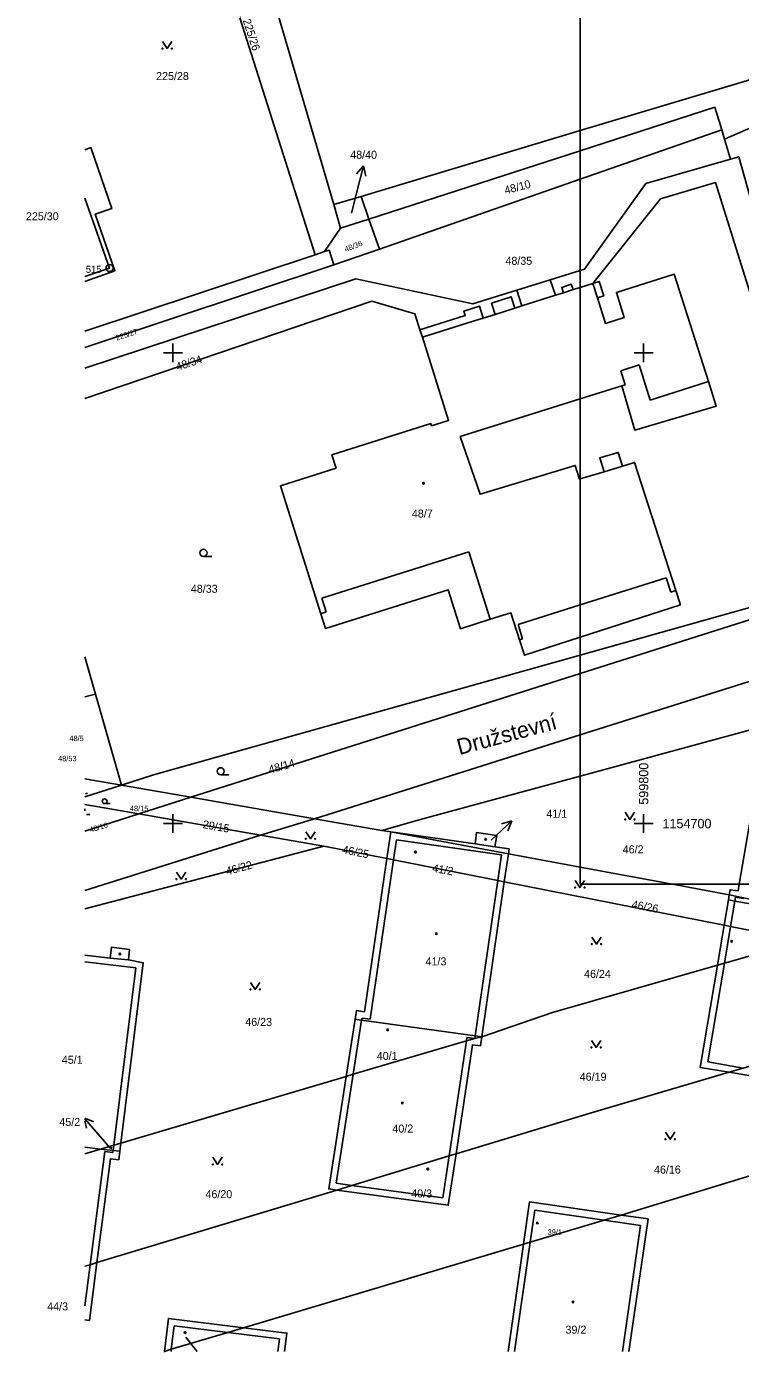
# Model space of a CAD drawing. Extents: x -599866 to -590076, y -1178039 to -1154526.
# Drawn here: x -599865.6 to -599789.7, y -1154756.1 to -1154615.4 of the extents above; entities that cross this region are included whole.
import ezdxf

# ---------------------------------------------------------------- set-up
doc = ezdxf.new("R2010")
doc.units = 0
for name, color, linetype in [('KN', 7, 'Continuous'), ('Rám', 7, 'Continuous'), ('Vrstva 5', 7, 'Continuous')]:
    doc.layers.add(name, color=color, linetype=linetype)

msp = doc.modelspace()

# ---------------------------------------------------------------- linework, layer by layer
at = {"layer": 'KN'}
for p, q in [((-599849.84, -1154592.53), (-599834.91, -1154639.59)), ((-599832.92, -1154634.27), (-599842.8, -1154600.57)), ((-599779.98, -1154622.34), (-599791.41, -1154627.32)), ((-599806.74, -1154631.58), (-599791.7, -1154626.34)), ((-599791.41, -1154627.32), (-599791.7, -1154626.34)), ((-599790.77, -1154629.45), (-599791.41, -1154627.32)), ((-599830.49, -1154633.05), (-599829.76, -1154630.14)), ((-599829.76, -1154630.14), (-599830.49, -1154630.99)), ((-599829.76, -1154630.14), (-599829.52, -1154631.23)), ((-599828.05, -1154639.01), (-599806.74, -1154631.58)), ((-599856.74, -1154641.01), (-599859.38, -1154633.6)), ((-599830.02, -1154633.4), (-599832.92, -1154634.27)), ((-599832.92, -1154634.27), (-599832.19, -1154636.77)), ((-599831.02, -1154635.16), (-599830.49, -1154633.05)), ((-599830.02, -1154633.4), (-599829.18, -1154635.8)), ((-599832.19, -1154636.77), (-599833.89, -1154639.25)), ((-599829.18, -1154635.8), (-599832.19, -1154636.77)), ((-599829.18, -1154635.8), (-599828.05, -1154639.01)), ((-599834.91, -1154639.59), (-599833.89, -1154639.25)), ((-599828.05, -1154639.01), (-599832.9, -1154640.67)), ((-599832.9, -1154640.67), (-599859.38, -1154649.44)), ((-599856.74, -1154641.01), (-599859.38, -1154641.89)), ((-599809.93, -1154642.24), (-599813.46, -1154643.34)), ((-599805.39, -1154642.63), (-599804.9, -1154644.17)), ((-599812.94, -1154645.02), (-599809.38, -1154643.89)), ((-599808.52, -1154643.62), (-599807.5, -1154643.3)), ((-599815.77, -1154645.92), (-599813.7, -1154645.26)), ((-599823.51, -1154648.36), (-599818.69, -1154646.84)), ((-599818.69, -1154646.84), (-599817.04, -1154646.32)), ((-599800.49, -1154651.29), (-599802.44, -1154651.91)), ((-599802.44, -1154651.91), (-599801.96, -1154653.41)), ((-599799.3, -1154655.03), (-599800.49, -1154651.29)), ((-599801.96, -1154653.41), (-599802.33, -1154653.52)), ((-599793.1, -1154653.06), (-599799.3, -1154655.03)), ((-599804.21, -1154662.63), (-599802.26, -1154662.04)), ((-599846.76, -1154671.63), (-599845.88, -1154671.63)), ((-599818.56, -1154671.14), (-599834.18, -1154676.08)), ((-599816.29, -1154678.31), (-599818.56, -1154671.14)), ((-599797.59, -1154673.91), (-599806.74, -1154676.78)), ((-599797.1, -1154675.43), (-599797.59, -1154673.91)), ((-599834.18, -1154676.08), (-599833.72, -1154677.53)), ((-599779.39, -1154675.37), (-599806.74, -1154684.06)), ((-599796.58, -1154675.26), (-599797.1, -1154675.43)), ((-599833.72, -1154677.53), (-599834.28, -1154677.71)), ((-599806.74, -1154676.78), (-599813.34, -1154678.85)), ((-599813.34, -1154678.85), (-599812.86, -1154680.37)), ((-599812.86, -1154680.37), (-599813.19, -1154680.48)), ((-599806.74, -1154684.06), (-599848.12, -1154697.2)), ((-599858.24, -1154686.27), (-599859.38, -1154686.55)), ((-599855.48, -1154695.93), (-599858.24, -1154686.27)), ((-599806.74, -1154694.96), (-599786.94, -1154689.6)), ((-599859.38, -1154695.26), (-599855.48, -1154695.93)), ((-599855.48, -1154695.93), (-599859.38, -1154697.17)), ((-599855.48, -1154695.93), (-599848.12, -1154697.2)), ((-599844.93, -1154694.82), (-599844.05, -1154694.82)), ((-599823.45, -1154699.48), (-599806.74, -1154694.96)), ((-599859.28, -1154696.84), (-599859.09, -1154696.77)), ((-599848.12, -1154697.2), (-599853.64, -1154698.96)), ((-599848.12, -1154697.2), (-599834.98, -1154699.48)), ((-599859.38, -1154697.96), (-599853.64, -1154698.96)), ((-599853.64, -1154698.96), (-599859.38, -1154700.79)), ((-599857.26, -1154697.88), (-599856.67, -1154697.88)), ((-599840.69, -1154701.22), (-599853.64, -1154698.96)), ((-599859.2, -1154699.05), (-599858.84, -1154699.05)), ((-599840.69, -1154701.22), (-599834.98, -1154699.48)), ((-599834.98, -1154699.48), (-599827.8, -1154700.72)), ((-599827.8, -1154700.72), (-599823.45, -1154699.48)), ((-599816.21, -1154701.77), (-599814.02, -1154699.72)), ((-599814.02, -1154699.72), (-599815.09, -1154700.04)), ((-599814.02, -1154699.72), (-599814.41, -1154700.77)), ((-599840.69, -1154701.22), (-599833.96, -1154702.4)), ((-599827.8, -1154700.72), (-599826.85, -1154700.87)), ((-599826.85, -1154700.87), (-599827.27, -1154703.72)), ((-599817.9, -1154702.14), (-599826.85, -1154700.87)), ((-599826.85, -1154700.87), (-599814.37, -1154703.21)), ((-599826.58, -1154703.86), (-599826.27, -1154701.73)), ((-599826.27, -1154701.73), (-599815.09, -1154703.32)), ((-599827.27, -1154703.72), (-599833.96, -1154702.4)), ((-599817.9, -1154702.14), (-599815.8, -1154702.47)), ((-599814.8, -1154706.18), (-599814.37, -1154703.21)), ((-599814.37, -1154703.21), (-599806.74, -1154704.63)), ((-599829.05, -1154720.77), (-599826.58, -1154703.86)), ((-599827.27, -1154703.72), (-599826.58, -1154703.86)), ((-599826.58, -1154703.86), (-599815.49, -1154706.05)), ((-599815.09, -1154703.32), (-599815.49, -1154706.05)), ((-599806.74, -1154704.63), (-599796.94, -1154706.45)), ((-599815.49, -1154706.05), (-599817.9, -1154722.54)), ((-599815.49, -1154706.05), (-599814.8, -1154706.18)), ((-599817.2, -1154722.64), (-599814.8, -1154706.18)), ((-599791.45, -1154710.79), (-599814.8, -1154706.18)), ((-599796.94, -1154706.45), (-599790.91, -1154707.57)), ((-599791, -1154708.11), (-599791.45, -1154710.79)), ((-599790.91, -1154707.57), (-599791, -1154708.11)), ((-599790.77, -1154710.92), (-599790.32, -1154708.23)), ((-599790.32, -1154708.23), (-599790.25, -1154707.82)), ((-599790.25, -1154707.82), (-599789.39, -1154707.96)), ((-599791.45, -1154710.79), (-599792.17, -1154715.04)), ((-599791.42, -1154714.83), (-599790.77, -1154710.92)), ((-599856.68, -1154714.3), (-599854.73, -1154714.47)), ((-599859.38, -1154714.67), (-599853.93, -1154715.33)), ((-599853.93, -1154715.33), (-599856.28, -1154734.14)), ((-599793.18, -1154725.32), (-599791.42, -1154714.83)), ((-599830.65, -1154720.78), (-599831.6, -1154726.85)), ((-599830.85, -1154726.63), (-599829.96, -1154720.88)), ((-599829.96, -1154720.88), (-599829.92, -1154720.65)), ((-599829.92, -1154720.65), (-599829.05, -1154720.77)), ((-599818.78, -1154722.72), (-599818.83, -1154723.08)), ((-599817.94, -1154722.82), (-599818.78, -1154722.72)), ((-599817.9, -1154722.54), (-599817.94, -1154722.82)), ((-599817.94, -1154722.82), (-599817.2, -1154722.64)), ((-599818.83, -1154723.08), (-599820.67, -1154735.3)), ((-599789.41, -1154725.96), (-599793.18, -1154725.32)), ((-599831.6, -1154726.85), (-599855.55, -1154733.93)), ((-599832.65, -1154738.2), (-599830.85, -1154726.63)), ((-599831.6, -1154726.85), (-599830.85, -1154726.63)), ((-599859.38, -1154731.3), (-599858.42, -1154731.69)), ((-599857.49, -1154733.53), (-599859.38, -1154731.35)), ((-599859.38, -1154731.57), (-599859.18, -1154732.35)), ((-599773.56, -1154732.78), (-599802.38, -1154741.58)), ((-599856.68, -1154734.48), (-599857.49, -1154733.53)), ((-599856.28, -1154734.14), (-599856.35, -1154734.72)), ((-599855.66, -1154734.8), (-599855.55, -1154733.93)), ((-599857.25, -1154734.82), (-599858.81, -1154746.85)), ((-599856.38, -1154734.93), (-599857.25, -1154734.82)), ((-599856.35, -1154734.72), (-599856.38, -1154734.93)), ((-599820.67, -1154735.3), (-599821.34, -1154739.76)), ((-599830.99, -1154738.43), (-599832.65, -1154738.2)), ((-599821.34, -1154739.76), (-599830.99, -1154738.43)), ((-599832.6, -1154738.92), (-599858.08, -1154746.63)), ((-599812.04, -1154744.46), (-599811.55, -1154741.06)), ((-599811.55, -1154741.06), (-599804.18, -1154742.12)), ((-599804.18, -1154742.12), (-599800.34, -1154742.67)), ((-599802.26, -1154756.06), (-599800.34, -1154742.67)), ((-599812.77, -1154744.68), (-599842.5, -1154753.54)), ((-599813.71, -1154756.06), (-599812.04, -1154744.46)), ((-599858.81, -1154746.85), (-599859.38, -1154751.23)), ((-599858.81, -1154746.85), (-599858.08, -1154746.63)), ((-599850.18, -1154755.83), (-599849.87, -1154753.34)), ((-599849.87, -1154753.34), (-599844.17, -1154754.04)), ((-599848.65, -1154754.53), (-599847.89, -1154755.49)), ((-599844.17, -1154754.04), (-599838.68, -1154754.72)), ((-599838.85, -1154756.06), (-599838.68, -1154754.72)), ((-599850.91, -1154756.05), (-599850.96, -1154756.06)), ((-599850.21, -1154756.06), (-599850.18, -1154755.83)), ((-599847.89, -1154755.49), (-599847.44, -1154756.06))]:
    msp.add_line(p, q, dxfattribs=at)
for points in [[(-599851.12, -1154616.95), (-599850.62, -1154617.7), (-599850.12, -1154616.95)], [(-599782.89, -1154620.22), (-599786.61, -1154620.37), (-599806.74, -1154626.41)], [(-599791.7, -1154626.34), (-599792.42, -1154623.92), (-599806.74, -1154628.55)], [(-599806.74, -1154626.41), (-599830.02, -1154633.4)], [(-599859.38, -1154628.44), (-599858.74, -1154628.22), (-599856.5, -1154634.69), (-599858.25, -1154635.3), (-599856.16, -1154641.3), (-599859.38, -1154642.42)], [(-599806.74, -1154628.55), (-599829.18, -1154635.8)], [(-599806.74, -1154641.25), (-599806.3, -1154641.11), (-599799.75, -1154632.01), (-599790.77, -1154629.45)], [(-599784.88, -1154646.97), (-599789.9, -1154629.2), (-599790.77, -1154629.45)], [(-599779.65, -1154674.5), (-599784.9, -1154657), (-599786.85, -1154655.89), (-599787.57, -1154653.53), (-599785.79, -1154652.94), (-599792.35, -1154631.92), (-599798.2, -1154633.66), (-599805.39, -1154642.63)], [(-599834.91, -1154639.59), (-599859.38, -1154647.72)], [(-599833.89, -1154639.25), (-599833.4, -1154639.09), (-599832.9, -1154640.67)], [(-599809.93, -1154642.24), (-599806.74, -1154641.25)], [(-599813.46, -1154643.34), (-599818.16, -1154644.81), (-599830.56, -1154642.16), (-599859.38, -1154651.63)], [(-599806.74, -1154643.06), (-599807.5, -1154643.3), (-599807.69, -1154642.73), (-599808.7, -1154643.07), (-599808.52, -1154643.62), (-599809.38, -1154643.89), (-599809.93, -1154642.24)], [(-599806.74, -1154654.91), (-599802.33, -1154653.52), (-599800.94, -1154658.22), (-599792.28, -1154655.66), (-599793.1, -1154653.06), (-599796.74, -1154641.67), (-599802.89, -1154643.6), (-599802.08, -1154646.27), (-599804.04, -1154646.89), (-599804.9, -1154644.17), (-599804.23, -1154643.95), (-599804.72, -1154642.42), (-599805.39, -1154642.63)], [(-599805.39, -1154642.63), (-599806.74, -1154643.06)], [(-599813.46, -1154643.34), (-599812.94, -1154645.02), (-599813.7, -1154645.26), (-599814.09, -1154644.05), (-599816.15, -1154644.74), (-599815.77, -1154645.92), (-599817.04, -1154646.32), (-599817.45, -1154645.05), (-599819.09, -1154645.58), (-599818.95, -1154646.04), (-599823.76, -1154647.57)], [(-599823.76, -1154647.57), (-599824.3, -1154645.86), (-599828.88, -1154644.53), (-599859.38, -1154654.85)], [(-599823.76, -1154647.57), (-599823.51, -1154648.36), (-599820.72, -1154657.18), (-599822.53, -1154657.75), (-599822.61, -1154657.52), (-599833.11, -1154660.84), (-599832.67, -1154662.25), (-599838.58, -1154664.12), (-599834.28, -1154677.71), (-599833.78, -1154679.29), (-599820.75, -1154675.17), (-599819.44, -1154679.31), (-599816.29, -1154678.31), (-599814.1, -1154677.62), (-599813.19, -1154680.48), (-599812.67, -1154682.13), (-599806.74, -1154680.22)], [(-599806.74, -1154663.4), (-599806.82, -1154663.42), (-599807.26, -1154661.96), (-599817.38, -1154665.03), (-599819.48, -1154658.91), (-599806.74, -1154654.91)], [(-599806.74, -1154680.22), (-599796.09, -1154676.78), (-599796.58, -1154675.26), (-599800.97, -1154661.65), (-599802.26, -1154662.04), (-599802.7, -1154660.58), (-599804.66, -1154661.17), (-599804.21, -1154662.63), (-599806.74, -1154663.4)], [(-599806.74, -1154690.57), (-599751.66, -1154673.18), (-599740.79, -1154669.9), (-599738.46, -1154669.48), (-599735.86, -1154669.61), (-599733.7, -1154670.53), (-599731.62, -1154671.85), (-599729.9, -1154673.34)], [(-599779.65, -1154674.5), (-599806.74, -1154682.11)], [(-599806.74, -1154682.11), (-599852.06, -1154694.84), (-599855.48, -1154695.93)], [(-599858.24, -1154686.27), (-599859.38, -1154682.29)], [(-599834.98, -1154699.48), (-599806.74, -1154690.57)], [(-599786.94, -1154689.6), (-599789.84, -1154706.45)], [(-599859.37, -1154698.44), (-599859.37, -1154698.66)], [(-599801.96, -1154698.8), (-599801.46, -1154699.55), (-599800.96, -1154698.8)], [(-599859.38, -1154707.11), (-599840.69, -1154701.22)], [(-599835.9, -1154700.87), (-599835.4, -1154701.62), (-599834.9, -1154700.87)], [(-599815.8, -1154702.47), (-599815.61, -1154701.27), (-599817.76, -1154700.96), (-599817.9, -1154702.14)], [(-599833.96, -1154702.4), (-599859.38, -1154709.04)], [(-599814.37, -1154703.21), (-599814.29, -1154702.67), (-599815.8, -1154702.47)], [(-599827.27, -1154703.72), (-599829.64, -1154719.98), (-599830.51, -1154719.86), (-599830.65, -1154720.78)], [(-599849.63, -1154705.15), (-599849.13, -1154705.9), (-599848.63, -1154705.15)], [(-599807.28, -1154706.04), (-599806.78, -1154706.79), (-599806.28, -1154706.04)], [(-599789.84, -1154706.45), (-599789.96, -1154707.16), (-599790.82, -1154707.02), (-599790.91, -1154707.57)], [(-599777.6, -1154710.42), (-599778.29, -1154710.3), (-599790.32, -1154708.23), (-599791, -1154708.11)], [(-599790.91, -1154707.57), (-599789.38, -1154707.88), (-599778.27, -1154710.18), (-599777.59, -1154710.33)], [(-599791.45, -1154710.79), (-599790.77, -1154710.92), (-599783.09, -1154712.44)], [(-599805.52, -1154712.05), (-599805.02, -1154712.8), (-599804.52, -1154712.05)], [(-599792.17, -1154715.04), (-599791.42, -1154714.83), (-599783.09, -1154712.44)], [(-599856.68, -1154714.3), (-599859.38, -1154713.97)], [(-599854.73, -1154714.47), (-599854.63, -1154713.38), (-599856.53, -1154713.11), (-599856.68, -1154714.3)], [(-599855.55, -1154733.93), (-599853.16, -1154714.78), (-599854.73, -1154714.47)], [(-599792.17, -1154715.04), (-599809.69, -1154720.07), (-599817.2, -1154722.64)], [(-599792.17, -1154715.04), (-599793.99, -1154725.89), (-599790.93, -1154726.41)], [(-599841.76, -1154716.87), (-599841.26, -1154717.62), (-599840.76, -1154716.87)], [(-599817.2, -1154722.64), (-599817.9, -1154722.54), (-599829.96, -1154720.88), (-599830.65, -1154720.78)], [(-599830.85, -1154726.63), (-599818.83, -1154723.08), (-599817.94, -1154722.82)], [(-599819.93, -1154735.08), (-599818.19, -1154723.5), (-599817.34, -1154723.6), (-599817.2, -1154722.64)], [(-599805.55, -1154723.02), (-599805.05, -1154723.77), (-599804.55, -1154723.02)], [(-599790.93, -1154726.41), (-599789.41, -1154725.96), (-599781.48, -1154723.62), (-599780.74, -1154723.39)], [(-599790.93, -1154726.41), (-599781.53, -1154728), (-599780.74, -1154723.39)], [(-599831.6, -1154726.85), (-599833.45, -1154738.8), (-599832.6, -1154738.92)], [(-599790.93, -1154726.41), (-599805.69, -1154730.77), (-599819.93, -1154735.08)], [(-599797.68, -1154732.78), (-599797.18, -1154733.53), (-599796.68, -1154732.78)], [(-599857.69, -1154734.56), (-599856.28, -1154734.14), (-599855.55, -1154733.93)], [(-599857.69, -1154734.56), (-599859.38, -1154734.36)], [(-599859.38, -1154735.06), (-599857.69, -1154734.56)], [(-599858.08, -1154746.63), (-599856.65, -1154735.6), (-599855.77, -1154735.71), (-599855.66, -1154734.8)], [(-599855.66, -1154734.8), (-599856.35, -1154734.72), (-599857.69, -1154734.56)], [(-599845.76, -1154735.44), (-599845.26, -1154736.19), (-599844.76, -1154735.44)], [(-599832.6, -1154738.92), (-599830.99, -1154738.43), (-599820.67, -1154735.3), (-599819.93, -1154735.08)], [(-599832.6, -1154738.92), (-599820.75, -1154740.54), (-599819.93, -1154735.08)], [(-599802.38, -1154741.58), (-599812.13, -1154740.18), (-599812.77, -1154744.68)], [(-599812.77, -1154744.68), (-599812.04, -1154744.46), (-599804.18, -1154742.12), (-599802.38, -1154741.58)], [(-599801.56, -1154756.06), (-599799.53, -1154741.99), (-599802.38, -1154741.58)], [(-599812.77, -1154744.68), (-599814.4, -1154756.06)], [(-599859.38, -1154752.7), (-599858.88, -1154752.76), (-599858.08, -1154746.63)], [(-599859.38, -1154747.02), (-599858.81, -1154746.85)], [(-599842.5, -1154753.54), (-599850.48, -1154752.56), (-599850.91, -1154756.05)], [(-599850.91, -1154756.05), (-599850.18, -1154755.83), (-599844.17, -1154754.04), (-599842.5, -1154753.54)], [(-599838.14, -1154756.06), (-599837.9, -1154754.11), (-599842.5, -1154753.54)], [(-599850.91, -1154756.05), (-599850.91, -1154756.06)]]:
    msp.add_lwpolyline(points, dxfattribs=at)
for centre, radius in [((-599851.12, -1154617.7), 0.05), ((-599850.12, -1154617.7), 0.05), ((-599856.74, -1154641.01), 0.375), ((-599856.74, -1154641.01), 0.015), ((-599823.38, -1154663.87), 0.0875), ((-599846.76, -1154671.25), 0.375), ((-599844.93, -1154694.44), 0.375), ((-599857.26, -1154697.63), 0.251), ((-599801.96, -1154699.55), 0.05), ((-599800.96, -1154699.55), 0.05), ((-599835.9, -1154701.62), 0.05), ((-599834.9, -1154701.62), 0.05), ((-599816.78, -1154701.67), 0.0875), ((-599824.24, -1154703.03), 0.0875), ((-599849.63, -1154705.9), 0.05), ((-599848.63, -1154705.9), 0.05), ((-599807.28, -1154706.79), 0.05), ((-599806.28, -1154706.79), 0.05), ((-599822.02, -1154711.69), 0.0875), ((-599805.52, -1154712.8), 0.05), ((-599804.52, -1154712.8), 0.05), ((-599790.64, -1154712.5), 0.0875), ((-599855.64, -1154713.85), 0.0875), ((-599841.76, -1154717.62), 0.05), ((-599840.76, -1154717.62), 0.05), ((-599827.2, -1154721.91), 0.0875), ((-599805.55, -1154723.77), 0.05), ((-599804.55, -1154723.77), 0.05), ((-599825.63, -1154729.68), 0.0875), ((-599797.68, -1154733.53), 0.05), ((-599796.68, -1154733.53), 0.05), ((-599856.56, -1154734.47), 0.0586), ((-599845.76, -1154736.19), 0.05), ((-599844.76, -1154736.19), 0.05), ((-599822.93, -1154736.7), 0.0875), ((-599811.29, -1154742.41), 0.0875), ((-599807.51, -1154750.81), 0.0875), ((-599848.71, -1154754.05), 0.0875)]:
    msp.add_circle(centre, radius, dxfattribs=at)
msp.add_arc((-599859.6, -1154698.55), 0.251, 334.5101, 25.4899, dxfattribs=at)
at = {"layer": 'Rám'}
for points in [[(-599806.74, -1154557.95), (-599806.74, -1154706.45)], [(-599806.74, -1154706.45), (-599701.74, -1154706.45)]]:
    msp.add_lwpolyline(points, dxfattribs=at)
at = {"layer": 'Vrstva 5'}
for p, q in [((-599850, -1154649), (-599850, -1154651)), ((-599800, -1154649), (-599800, -1154651)), ((-599849, -1154650), (-599851, -1154650)), ((-599799, -1154650), (-599801, -1154650)), ((-599850, -1154699), (-599850, -1154701)), ((-599800, -1154699), (-599800, -1154701)), ((-599800, -1154701), (-599800, -1154699)), ((-599849, -1154700), (-599851, -1154700)), ((-599799, -1154700), (-599801, -1154700)), ((-599801, -1154700), (-599799, -1154700))]:
    msp.add_line(p, q, dxfattribs=at)

# ---------------------------------------------------------------- texts
at = {"layer": 'KN'}
for s, height, rotation, p in [('225/26', 0.85, 288, (-599842.6, -1154614.7)), ('48/10', 0.85, 15, (-599814.67, -1154633.18)), ('48/36', 0.57, 21, (-599831.65, -1154639.3)), ('225/27', 0.57, 18, (-599855.98, -1154648.72)), ('48/34', 0.85, 18, (-599849.53, -1154651.92)), ('Družstevní', 1.7, 15, (-599819.58, -1154692.73)), ('48/14', 0.85, 16, (-599839.71, -1154694.7)), ('48/16', 0.57, 17, (-599858.76, -1154700.96)), ('29/15', 0.85, 350, (-599846.89, -1154700.47)), ('46/25', 0.85, 349, (-599832.07, -1154703.15)), ('46/22', 0.85, 15, (-599844.25, -1154705.49)), ('41/2', 0.85, 350, (-599822.49, -1154705.12)), ('46/26', 0.85, 349, (-599801.32, -1154708.95))]:
    msp.add_text(s, height=height, rotation=rotation, dxfattribs=at).set_placement(p)
for s, height, p in [('225/28', 0.85, (-599851.79, -1154621.04)), ('48/40', 0.85, (-599831.17, -1154629.4)), ('225/30', 0.85, (-599865.62, -1154635.93)), ('48/35', 0.85, (-599814.68, -1154640.66)), ('515', 0.75, (-599859.26, -1154641.51)), ('48/7', 0.85, (-599824.62, -1154667.5)), ('48/33', 0.85, (-599848.1, -1154675.49)), ('48/5', 0.57, (-599861.01, -1154691.24)), ('48/53', 0.57, (-599862.21, -1154693.38)), ('48/15', 0.57, (-599854.58, -1154698.68)), ('41/1', 0.85, (-599810.33, -1154699.38)), ('46/2', 0.85, (-599802.22, -1154703.16)), ('41/3', 0.85, (-599823.17, -1154715.06)), ('46/24', 0.85, (-599806.33, -1154716.39)), ('46/23', 0.85, (-599842.32, -1154721.49)), ('40/1', 0.85, (-599828.35, -1154725.1)), ('45/1', 0.85, (-599861.81, -1154725.51)), ('46/19', 0.85, (-599806.79, -1154727.31)), ('45/2', 0.85, (-599862.07, -1154732.11)), ('40/2', 0.85, (-599826.69, -1154732.81)), ('46/16', 0.85, (-599798.9, -1154737.17)), ('46/20', 0.85, (-599846.55, -1154739.78)), ('40/3', 0.85, (-599824.69, -1154739.71)), ('39/1', 0.57, (-599810.2, -1154743.67)), ('44/3', 0.85, (-599863.36, -1154751.7)), ('39/2', 0.85, (-599808.3, -1154754.17))]:
    msp.add_text(s, height=height, dxfattribs=at).set_placement(p)
at = {"layer": 'Vrstva 5'}
msp.add_text('599800', height=1, rotation=90, dxfattribs=at).set_placement((-599799.5, -1154698))
msp.add_text('1154700', height=1, dxfattribs=at).set_placement((-599798, -1154700.5))

doc.saveas('drawing.dxf')
